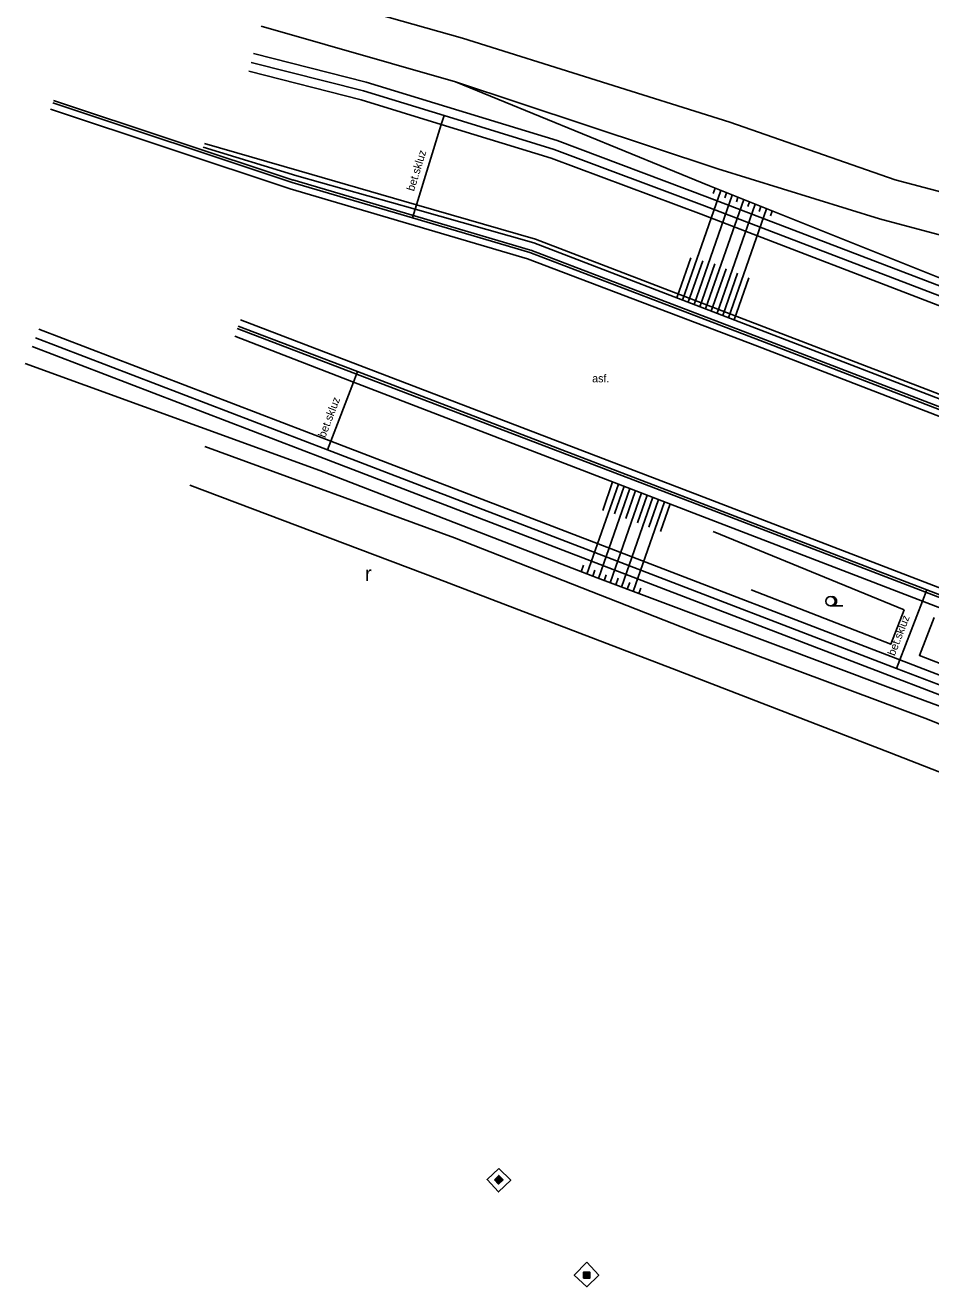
# Model space of a CAD drawing. Extents: x -539244 to -537359, y -1183785 to -1181851.
# Drawn here: x -539244.3 to -539170.8, y -1182571.1 to -1182468.6 of the extents above; entities that cross this region are included whole.
import ezdxf

# ---------------------------------------------------------------- set-up
doc = ezdxf.new("R2010")
doc.units = 0
for name, color, linetype in [('Vrstva 10', 7, 'Continuous'), ('Vrstva 11', 7, 'Continuous'), ('Vrstva 14', 7, 'Continuous'), ('Vrstva 15', 7, 'Continuous'), ('Vrstva 21', 7, 'Continuous'), ('Vrstva 25', 7, 'Continuous'), ('Vrstva 36', 7, 'Continuous'), ('Vrstva 40', 7, 'Continuous'), ('Vrstva 7', 7, 'Continuous'), ('Vrstva 9', 7, 'Continuous')]:
    doc.layers.add(name, color=color, linetype=linetype)

msp = doc.modelspace()

# ---------------------------------------------------------------- linework, layer by layer
at = {"layer": 'Vrstva 10'}
for p, q in [((-539242.268, -1182475.422), (-539222.798, -1182481.886)), ((-539222.798, -1182481.886), (-539203.522, -1182487.585)), ((-539203.522, -1182487.585), (-539184.852, -1182494.684)), ((-539189.55, -1182506.804), (-539226.842, -1182492.543)), ((-539184.852, -1182494.684), (-539147.506, -1182509.059)), ((-539152.164, -1182521.178), (-539189.55, -1182506.804))]:
    msp.add_line(p, q, dxfattribs=at)
at = {"layer": 'Vrstva 11'}
for p, q in [((-539224.221, -1182465.305), (-539208.816, -1182469.656)), ((-539225.173, -1182468.683), (-539209.369, -1182473.209)), ((-539208.816, -1182469.656), (-539187.085, -1182476.493)), ((-539225.775, -1182470.9), (-539216.634, -1182473.228)), ((-539226.157, -1182472.35), (-539217.038, -1182474.672)), ((-539216.634, -1182473.228), (-539210.09, -1182475.226)), ((-539209.369, -1182473.209), (-539188.066, -1182480.259)), ((-539217.038, -1182474.672), (-539210.53, -1182476.66)), ((-539222.632, -1182481.368), (-539242.092, -1182474.902)), ((-539210.09, -1182475.226), (-539201.13, -1182477.981)), ((-539210.53, -1182476.66), (-539201.614, -1182479.401)), ((-539173.677, -1182481.156), (-539187.085, -1182476.493)), ((-539201.13, -1182477.981), (-539188.9, -1182482.563)), ((-539201.614, -1182479.401), (-539189.432, -1182483.965)), ((-539188.066, -1182480.259), (-539174.951, -1182484.341)), ((-539140.319, -1182490.011), (-539173.677, -1182481.156)), ((-539188.9, -1182482.563), (-539164.47, -1182491.933)), ((-539189.432, -1182483.965), (-539165.008, -1182493.334)), ((-539184.634, -1182494.217), (-539203.33, -1182487.062)), ((-539243.223, -1182493.302), (-539219.515, -1182502.395)), ((-539243.761, -1182494.702), (-539220.053, -1182503.795)), ((-539209.459, -1182510.248), (-539229.725, -1182502.806)), ((-539219.515, -1182502.395), (-539197.084, -1182511.005)), ((-539220.053, -1182503.795), (-539197.622, -1182512.405)), ((-539230.962, -1182505.965), (-539210.808, -1182513.558)), ((-539189.522, -1182518.05), (-539209.459, -1182510.248)), ((-539197.084, -1182511.005), (-539173.281, -1182520.147)), ((-539197.622, -1182512.405), (-539173.819, -1182521.547)), ((-539210.808, -1182513.558), (-539191.794, -1182520.858)), ((-539171.057, -1182524.969), (-539189.522, -1182518.05)), ((-539173.281, -1182520.147), (-539157.63, -1182526.149)), ((-539191.794, -1182520.858), (-539174.139, -1182527.657)), ((-539173.819, -1182521.547), (-539158.171, -1182527.548)), ((-539150.755, -1182533.124), (-539171.057, -1182524.969)), ((-539174.139, -1182527.657), (-539152.44, -1182536.201))]:
    msp.add_line(p, q, dxfattribs=at)
for points in [[(-539203.33, -1182487.062), (-539212.878, -1182484.245), (-539222.632, -1182481.368)], [(-539126.967, -1182497.335), (-539164.911, -1182487.005), (-539174.951, -1182484.341)], [(-539189.714, -1182507.307), (-539217.344, -1182496.741), (-539227.034, -1182493.036)], [(-539147.32, -1182508.584), (-539167.838, -1182500.684), (-539184.634, -1182494.217)], [(-539152.354, -1182521.681), (-539171.096, -1182514.47), (-539189.714, -1182507.307)]]:
    msp.add_lwpolyline(points, dxfattribs=at)
at = {"layer": 'Vrstva 14'}
for p, q in [((-539225.966, -1182471.625), (-539216.836, -1182473.95)), ((-539209.369, -1182473.209), (-539188.751, -1182481.664)), ((-539216.836, -1182473.95), (-539210.31, -1182475.943)), ((-539210.31, -1182475.943), (-539201.372, -1182478.691)), ((-539229.862, -1182478.521), (-539222.272, -1182480.836)), ((-539201.372, -1182478.691), (-539189.166, -1182483.264)), ((-539188.751, -1182481.664), (-539164.252, -1182491.445)), ((-539212.878, -1182484.245), (-539212.664, -1182483.553)), ((-539212.664, -1182483.553), (-539212.55, -1182483.184)), ((-539189.166, -1182483.264), (-539164.738, -1182492.634)), ((-539243.492, -1182494.002), (-539219.784, -1182503.095)), ((-539220.397, -1182504.777), (-539244.321, -1182496.075)), ((-539217.344, -1182496.741), (-539217.667, -1182497.582)), ((-539217.667, -1182497.582), (-539219.515, -1182502.395)), ((-539219.515, -1182502.395), (-539219.784, -1182503.095)), ((-539219.784, -1182503.095), (-539197.353, -1182511.705)), ((-539197.881, -1182513.494), (-539220.397, -1182504.777)), ((-539197.353, -1182511.705), (-539173.55, -1182520.847)), ((-539174.242, -1182522.361), (-539197.881, -1182513.494)), ((-539171.096, -1182514.47), (-539171.443, -1182515.371)), ((-539173.55, -1182520.847), (-539157.942, -1182526.833)), ((-539155.376, -1182529.294), (-539174.242, -1182522.361))]:
    msp.add_line(p, q, dxfattribs=at)
for points in [[(-539212.55, -1182483.184), (-539210.53, -1182476.66), (-539210.31, -1182475.943)], [(-539222.272, -1182480.836), (-539212.664, -1182483.553), (-539203.011, -1182486.282)], [(-539203.011, -1182486.282), (-539167.543, -1182499.92), (-539147.002, -1182507.818)], [(-539227.308, -1182493.872), (-539217.667, -1182497.582), (-539171.443, -1182515.371), (-539152.698, -1182522.585)], [(-539171.443, -1182515.371), (-539173.281, -1182520.147), (-539173.55, -1182520.847)]]:
    msp.add_lwpolyline(points, dxfattribs=at)
at = {"layer": 'Vrstva 15'}
for p, q in [((-539190.935, -1182490.926), (-539187.831, -1182482.031)), ((-539190.001, -1182491.284), (-539186.902, -1182482.402)), ((-539189.067, -1182491.644), (-539185.972, -1182482.773)), ((-539188.447, -1182482.277), (-539188.296, -1182481.846)), ((-539187.507, -1182482.62), (-539187.366, -1182482.217)), ((-539186.562, -1182482.947), (-539186.437, -1182482.588)), ((-539188.134, -1182492.002), (-539185.043, -1182483.144)), ((-539187.2, -1182492.362), (-539184.113, -1182483.516)), ((-539185.639, -1182483.337), (-539185.507, -1182482.959)), ((-539184.715, -1182483.723), (-539184.578, -1182483.33)), ((-539183.784, -1182484.089), (-539183.649, -1182483.701)), ((-539191.402, -1182490.746), (-539190.267, -1182487.492)), ((-539190.468, -1182491.105), (-539189.29, -1182487.729)), ((-539189.534, -1182491.464), (-539188.318, -1182487.979)), ((-539188.6, -1182491.823), (-539187.405, -1182488.397)), ((-539187.667, -1182492.182), (-539186.47, -1182488.753)), ((-539186.733, -1182492.541), (-539185.542, -1182489.126)), ((-539198.699, -1182513.177), (-539196.147, -1182505.864)), ((-539197.765, -1182513.538), (-539195.213, -1182506.224)), ((-539197.423, -1182508.007), (-539196.613, -1182505.685)), ((-539196.463, -1182508.289), (-539195.68, -1182506.044)), ((-539195.536, -1182508.667), (-539194.746, -1182506.403)), ((-539196.829, -1182513.889), (-539194.28, -1182506.583)), ((-539195.892, -1182514.24), (-539193.346, -1182506.942)), ((-539194.956, -1182514.591), (-539192.412, -1182507.301)), ((-539194.6, -1182509.017), (-539193.813, -1182506.762)), ((-539193.665, -1182509.375), (-539192.879, -1182507.122)), ((-539192.728, -1182509.726), (-539191.945, -1182507.481)), ((-539199.165, -1182512.997), (-539198.976, -1182512.455)), ((-539198.232, -1182513.358), (-539198.06, -1182512.866)), ((-539197.297, -1182513.713), (-539197.135, -1182513.25)), ((-539196.36, -1182514.064), (-539196.166, -1182513.508)), ((-539195.424, -1182514.416), (-539195.232, -1182513.866)), ((-539194.487, -1182514.767), (-539194.329, -1182514.313))]:
    msp.add_line(p, q, dxfattribs=at)
at = {"layer": 'Vrstva 21'}
for points in [[(-539172.94, -1182516.08), (-539188.46, -1182509.73)], [(-539185.37, -1182514.46), (-539174.027, -1182518.873), (-539172.94, -1182516.08)], [(-539170.5, -1182516.7), (-539171.698, -1182519.779), (-539163.47, -1182522.98), (-539156.86, -1182525.35)]]:
    msp.add_lwpolyline(points, dxfattribs=at)
at = {"layer": 'Vrstva 25'}
for points in [[(-539206.223, -1182562.354), (-539205.876, -1182562.713), (-539205.517, -1182562.366), (-539205.864, -1182562.007)], [(-539206.153, -1182562.355), (-539205.875, -1182562.643), (-539205.587, -1182562.365), (-539205.865, -1182562.077)], [(-539206.082, -1182562.356), (-539205.874, -1182562.572), (-539205.658, -1182562.364), (-539205.866, -1182562.148)], [(-539206.011, -1182562.358), (-539205.872, -1182562.501), (-539205.729, -1182562.362), (-539205.868, -1182562.219)], [(-539205.941, -1182562.359), (-539205.871, -1182562.431), (-539205.799, -1182562.361), (-539205.869, -1182562.289)], [(-539198.97, -1182570.36), (-539198.47, -1182570.36), (-539198.47, -1182569.86), (-539198.97, -1182569.86)], [(-539198.92, -1182570.31), (-539198.52, -1182570.31), (-539198.52, -1182569.91), (-539198.92, -1182569.91)], [(-539198.87, -1182570.26), (-539198.57, -1182570.26), (-539198.57, -1182569.96), (-539198.87, -1182569.96)], [(-539198.82, -1182570.21), (-539198.62, -1182570.21), (-539198.62, -1182570.01), (-539198.82, -1182570.01)], [(-539198.77, -1182570.16), (-539198.67, -1182570.16), (-539198.67, -1182570.06), (-539198.77, -1182570.06)]]:
    msp.add_lwpolyline(points, close=True, dxfattribs=at)
at = {"layer": 'Vrstva 36'}
msp.add_line((-539178.922, -1182515.757), (-539177.922, -1182515.757), dxfattribs=at)
msp.add_circle((-539178.922, -1182515.382), 0.375, dxfattribs=at)
msp.add_arc((-539178.797, -1182515.382), 0.375, 260.40593, 99.59407, dxfattribs=at)
at = {"layer": 'Vrstva 7'}
msp.add_line((-539222.063, -1182480.427), (-539229.762, -1182478.223), dxfattribs=at)
for points in [[(-539202.867, -1182485.991), (-539212.55, -1182483.184), (-539222.063, -1182480.427)], [(-539146.861, -1182507.464), (-539167.414, -1182499.584), (-539202.867, -1182485.991)], [(-539205.86, -1182561.44), (-539204.89, -1182562.39), (-539205.88, -1182563.35), (-539206.81, -1182562.33), (-539205.86, -1182561.44)], [(-539198.72, -1182569.06), (-539197.74, -1182570.12), (-539198.72, -1182571.05), (-539199.73, -1182570.1), (-539198.72, -1182569.06)]]:
    msp.add_lwpolyline(points, dxfattribs=at)
at = {"layer": 'Vrstva 9'}
for p, q in [((-539222.569, -1182481.178), (-539242.029, -1182474.712)), ((-539203.273, -1182486.87), (-539222.575, -1182481.176)), ((-539184.563, -1182494.03), (-539203.259, -1182486.875)), ((-539227.105, -1182493.223), (-539189.786, -1182507.494)), ((-539147.248, -1182508.397), (-539184.562, -1182494.03)), ((-539189.786, -1182507.494), (-539152.426, -1182521.868))]:
    msp.add_line(p, q, dxfattribs=at)

# ---------------------------------------------------------------- texts
at = {"layer": 'Vrstva 36'}
msp.add_text('r', height=1.2, dxfattribs=at).set_placement((-539216.728, -1182513.735))
at = {"layer": 'Vrstva 40'}
for rotation, p in [(72.81195, (-539212.748, -1182482.133)), (68.99271, (-539219.959, -1182502.156)), (68.95226, (-539173.708, -1182519.865))]:
    msp.add_text('bet.skluz', height=0.65, rotation=rotation, dxfattribs=at).set_placement(p)
msp.add_text('asf.', height=0.65, dxfattribs=at).set_placement((-539198.282, -1182497.608))

doc.saveas('drawing.dxf')
